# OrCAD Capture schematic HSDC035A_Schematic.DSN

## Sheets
1 PAGE3 - HARDWARE: title: TUSB1002AEVM  / HARDWARE; rev: A; note: HSDC035
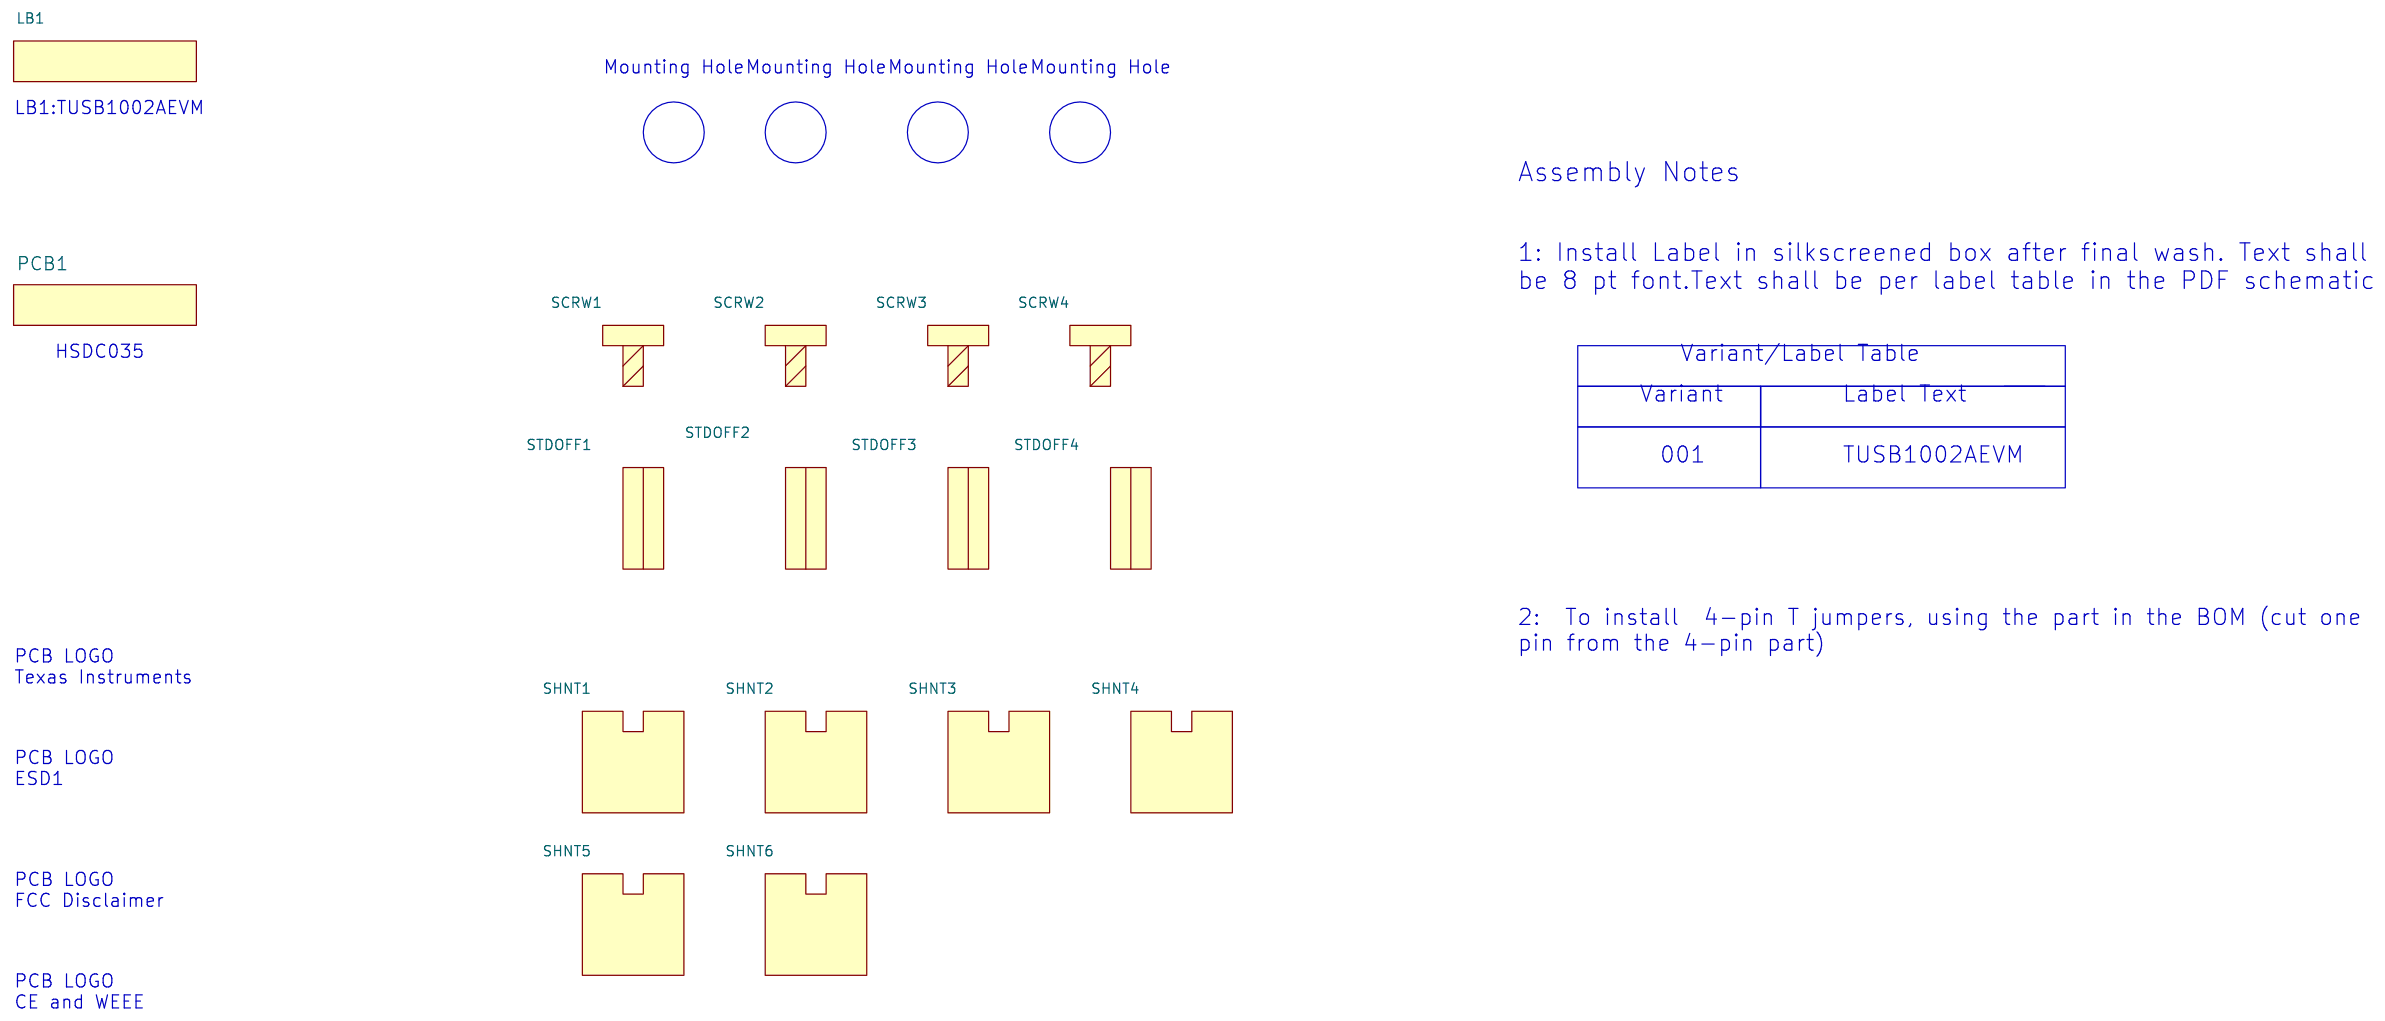
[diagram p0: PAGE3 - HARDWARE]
2 PAGE2 - CONFIG: size B; title: TUSB1002AEVM  / CONFIG; note: 6590969
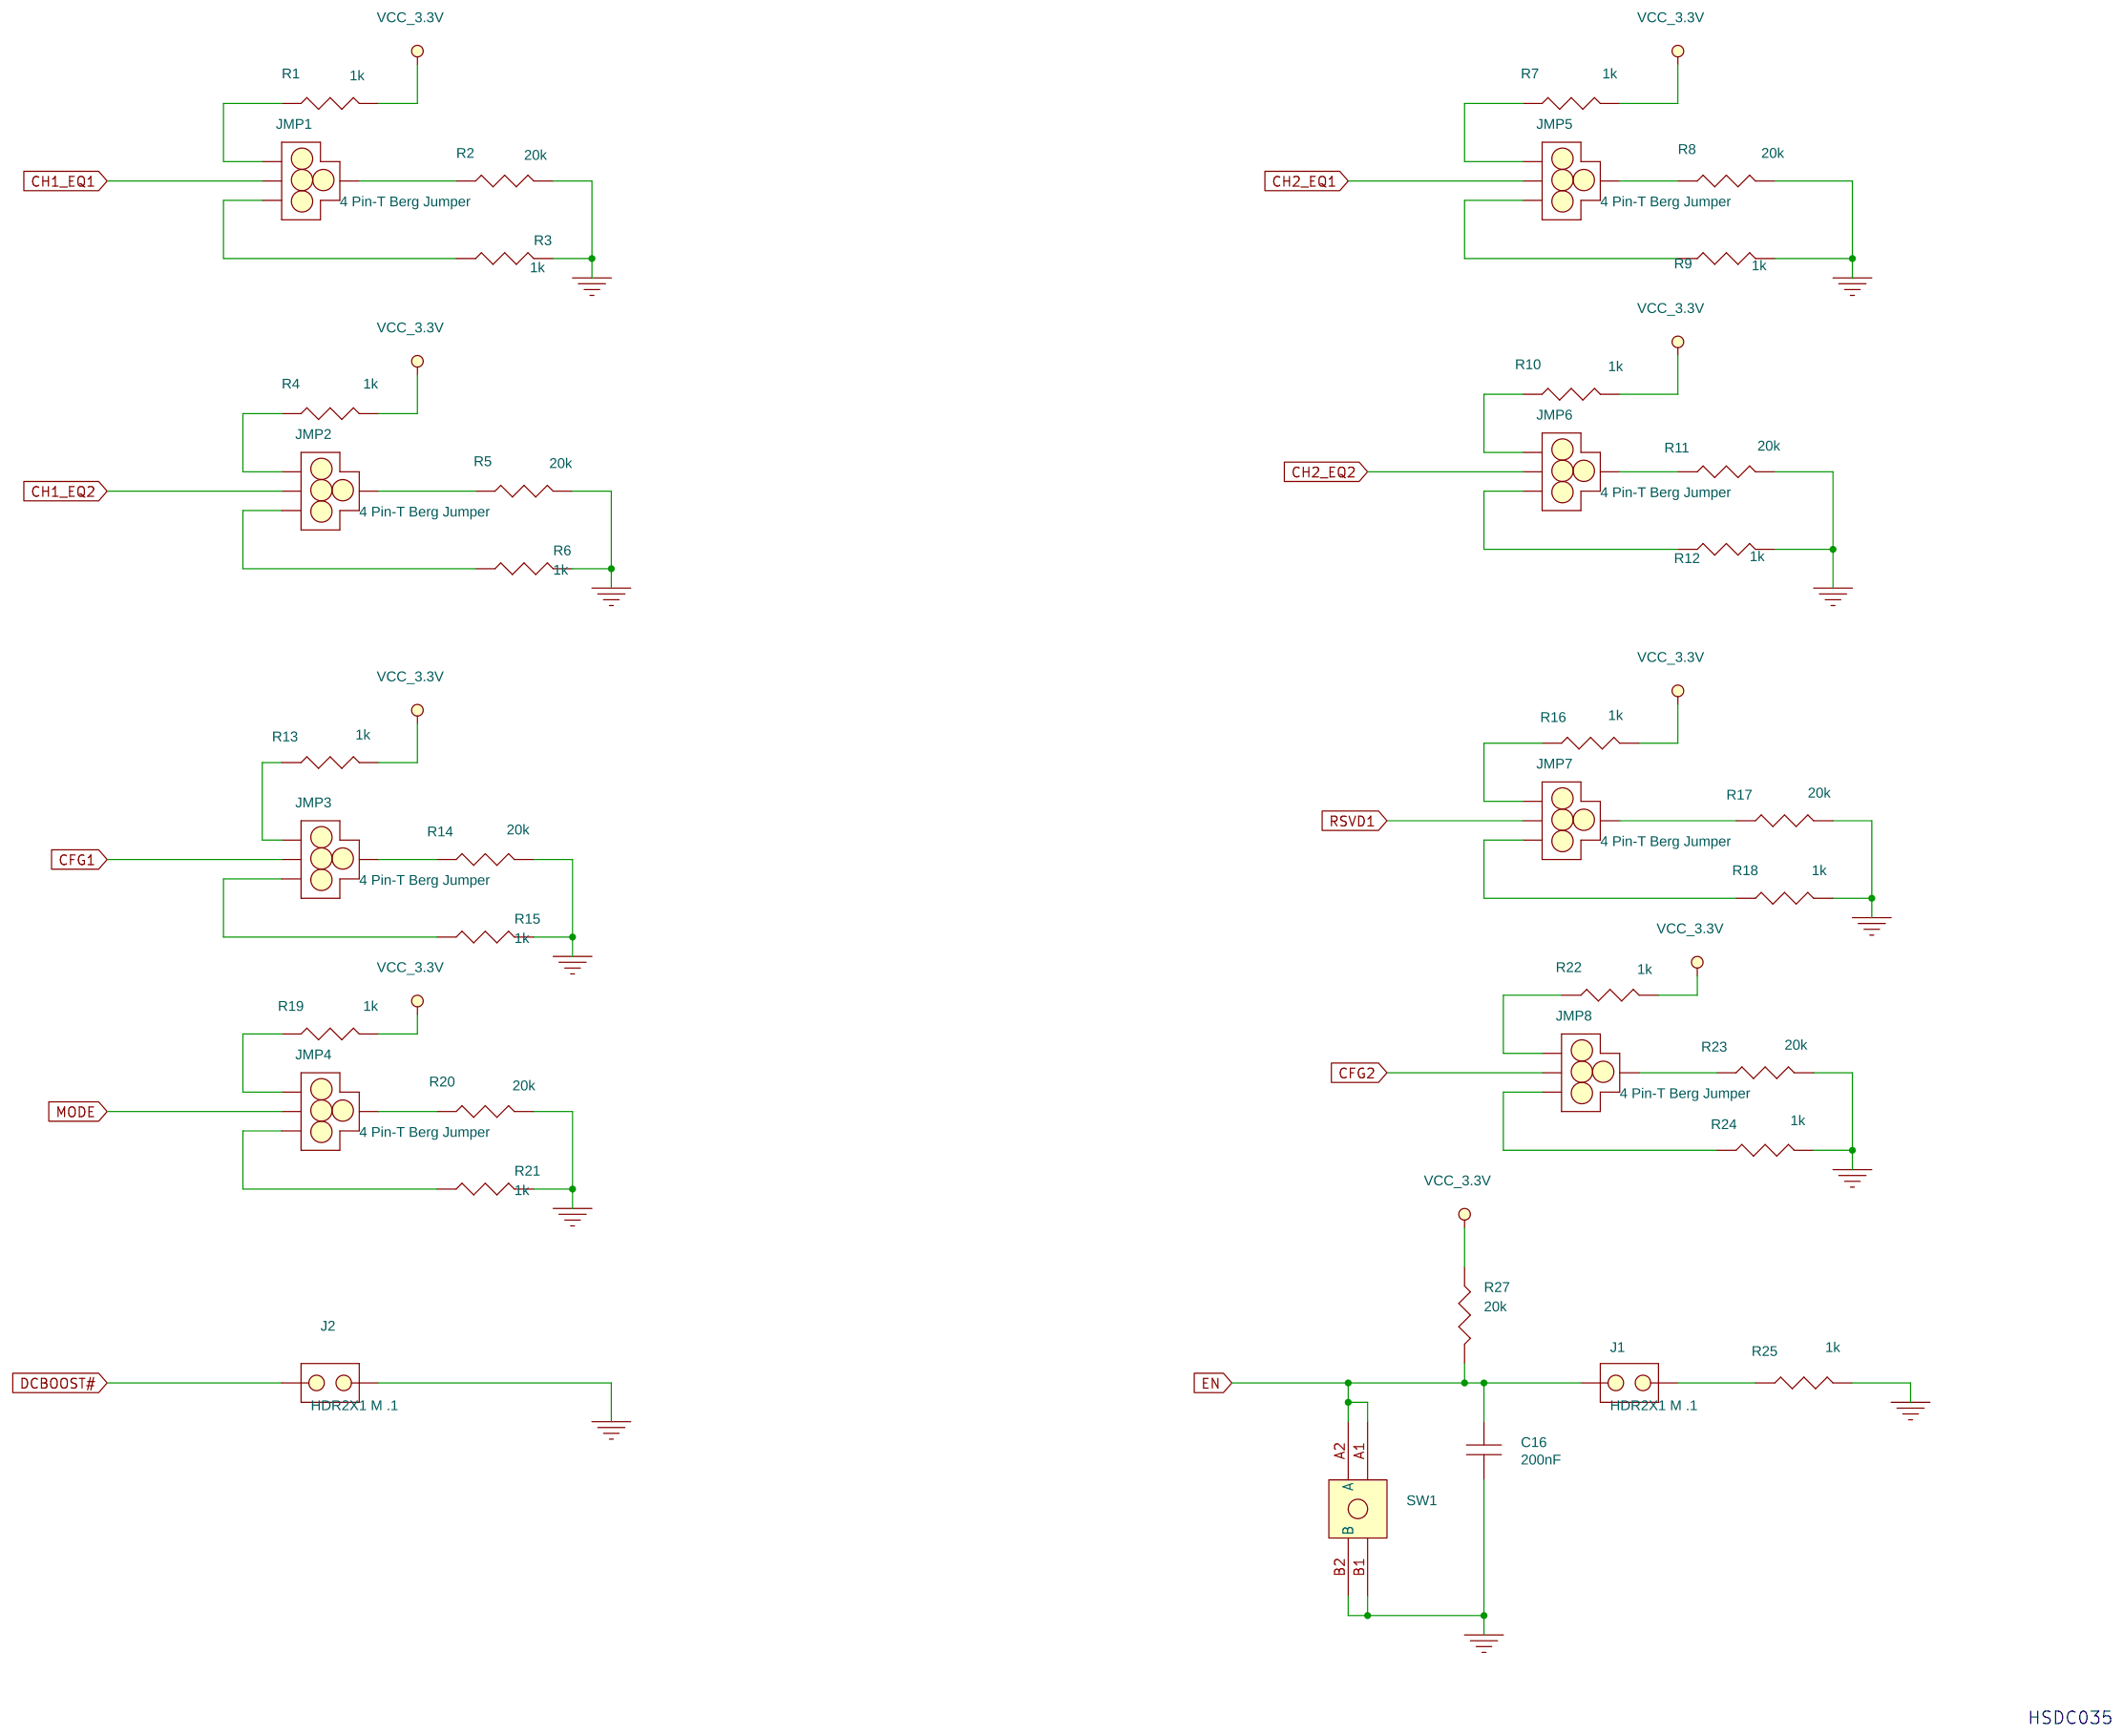
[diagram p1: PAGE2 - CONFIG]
3 PAGE1 - HighSpeed/Power: size B; title: TUSB1002AEVM / High-Speed/Power; note: 6590969
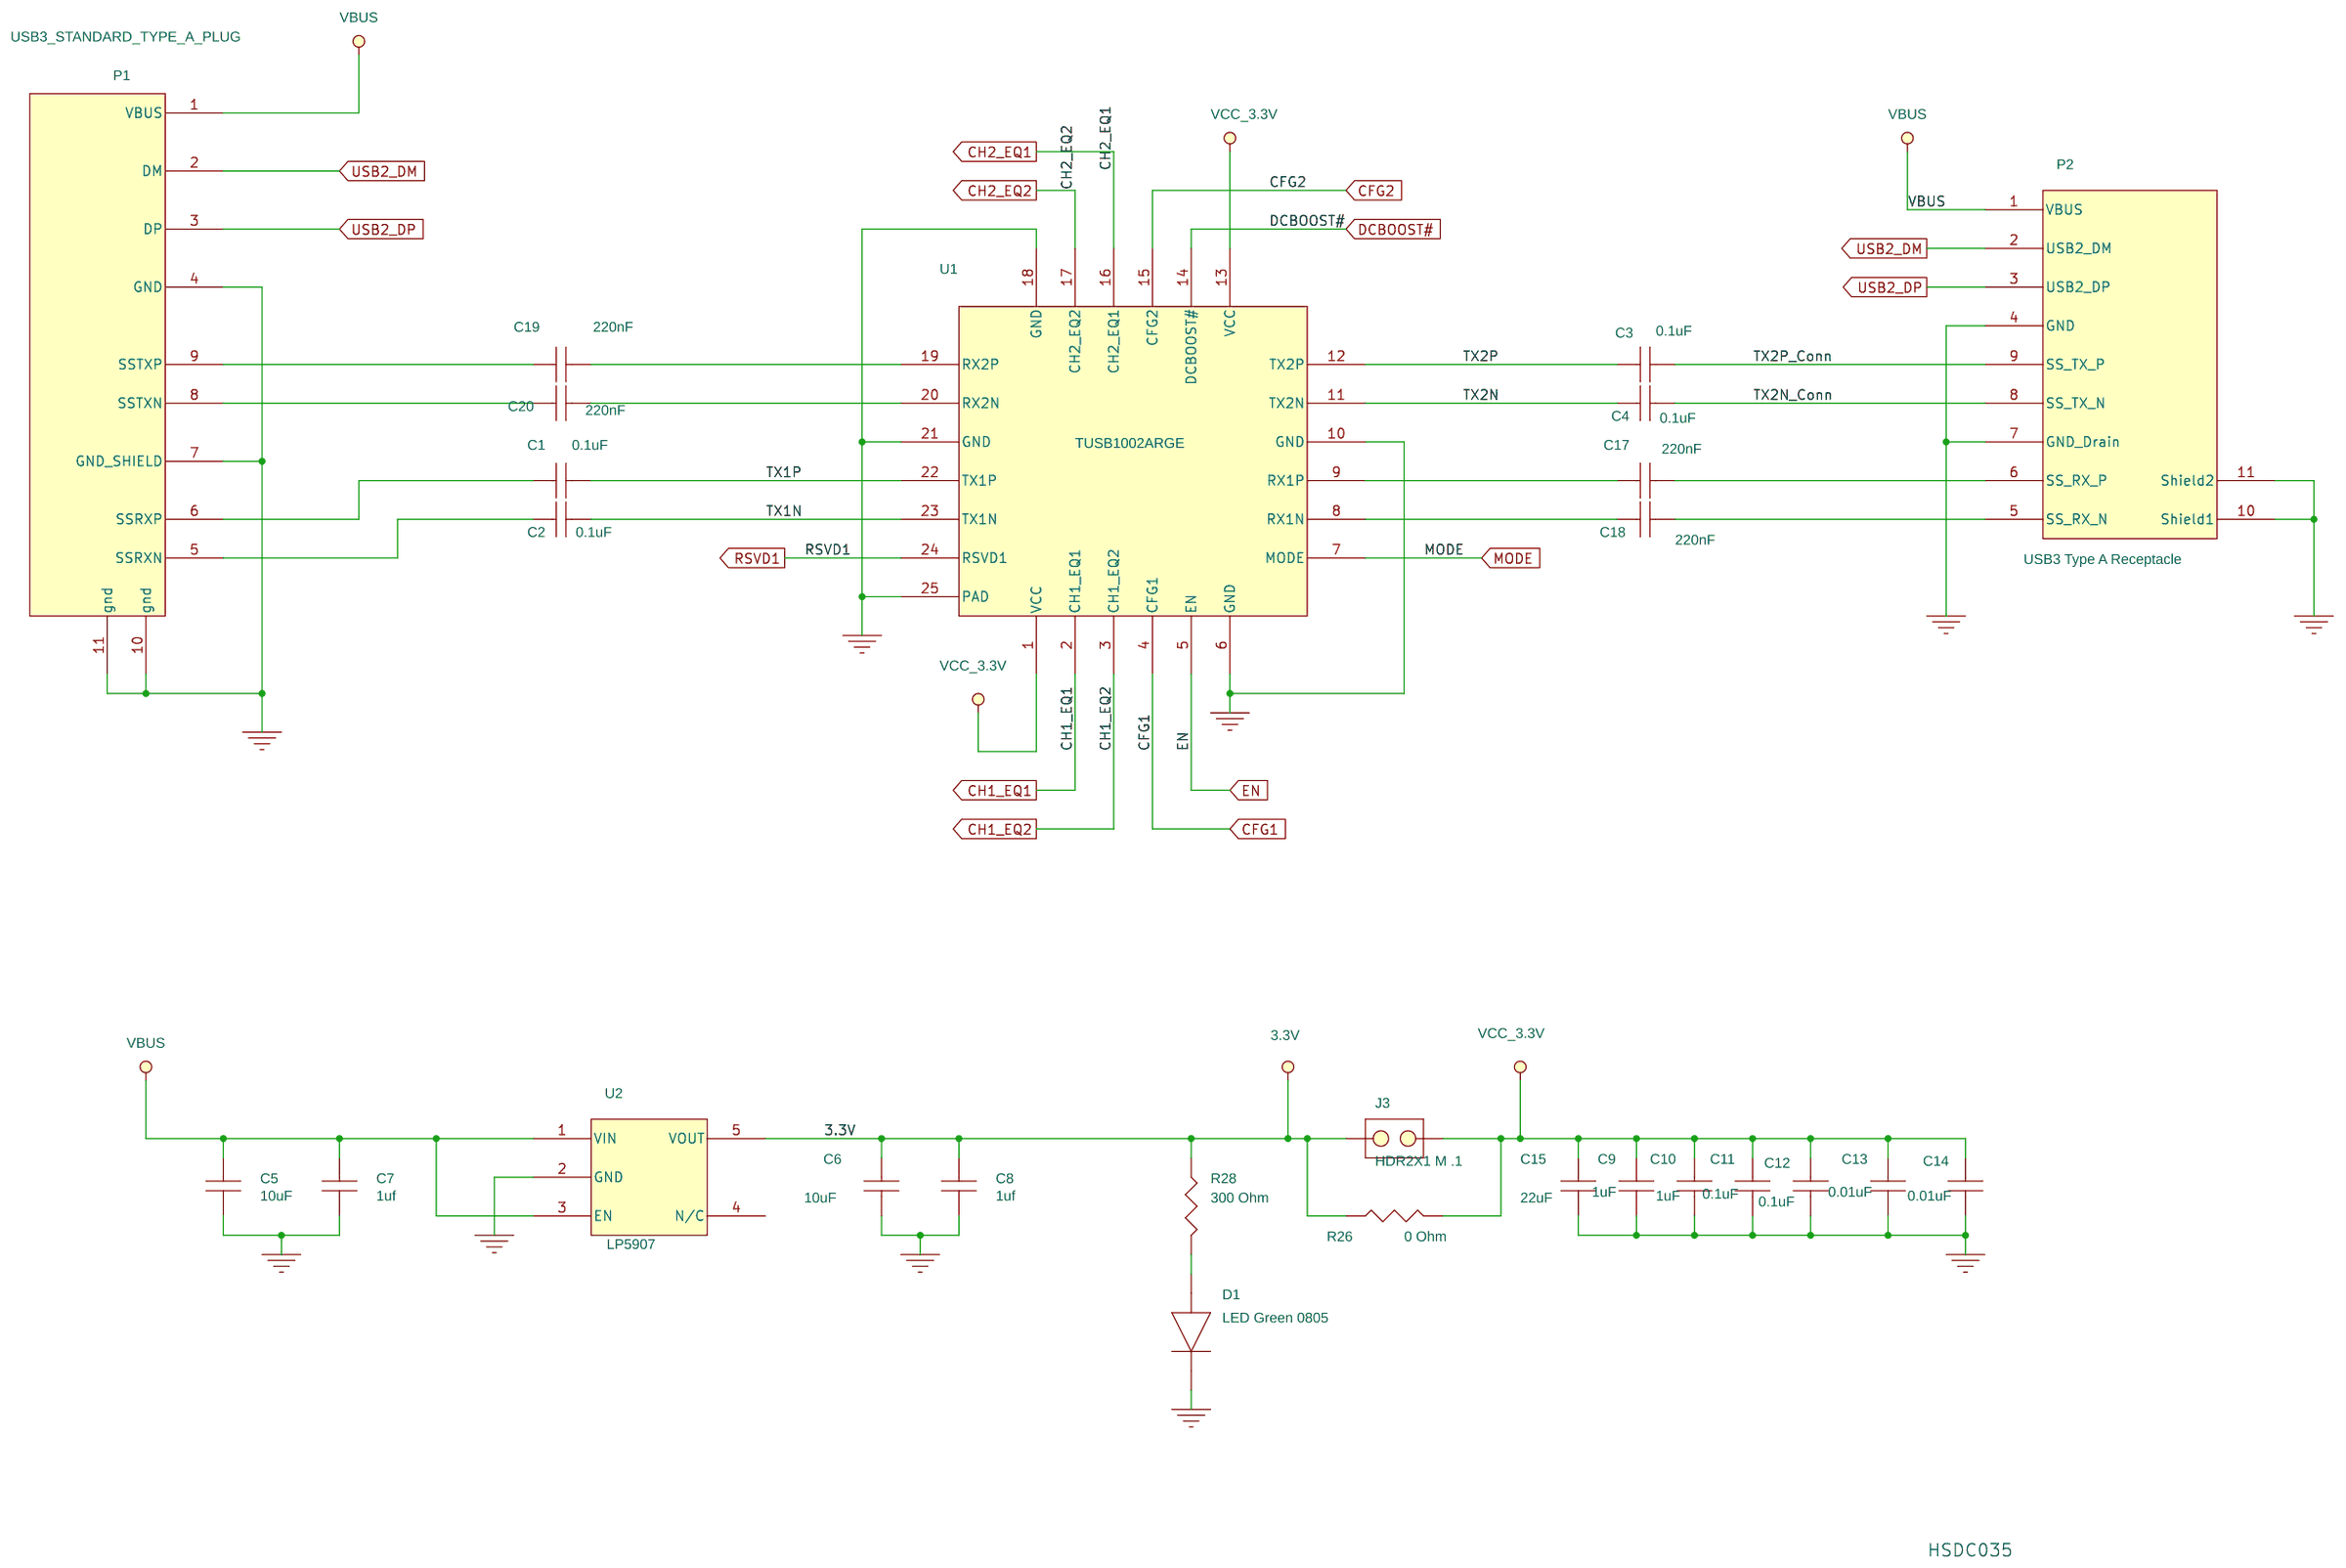
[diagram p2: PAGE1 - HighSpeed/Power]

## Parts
sheet PAGE1 - HighSpeed/Power
C1  0.1uF  [C0201]
C2  0.1uF  [C0201]
C3  0.1uF  [C0201]
C4  0.1uF  [C0201]
C5  10uF  [C0805]
C6  10uF  [C0805]
C7  1uf  [C0603]
C8  1uf  [C0603]
C9  1uF  [C0201]
C10  1uF  [C0201]
C11  0.1uF  [C0201]
C12  0.1uF  [C0201]
C13  0.01uF  [C0201]
C14  0.01uF  [C0201]
C15  22uF  [C0805]
C17  220nF  [C0201]
C18  220nF  [C0201]
C19  220nF  [C0201]
C20  220nF  [C0201]
D1  LED Green 0805  [led_0805]
J3  HDR2X1 M .1  [HDR_THVT_1x2_100]
P1  USB3_STANDARD_TYPE_A_PLUG  [CON_SMRT_USB3A_AMP]
P2  USB3 Type A Receptacle  [USB3_TYPEA]
R26  0 Ohm  [R0805]
R28  300 Ohm  [R0402]
U1  TUSB1002ARGE  [SKT_TUSB1002RGE]
U2  LP5907  [DBV_R-PDSO-G5]
sheet PAGE2 - CONFIG
C16  200nF  [C0402]
J1  HDR2X1 M .1  [HDR_THVT_1x2_100]
J2  HDR2X1 M .1  [HDR_THVT_1x2_100]
JMP1  4 Pin-T Berg Jumper  [berg2x3tee]
JMP2  4 Pin-T Berg Jumper  [berg2x3tee]
JMP3  4 Pin-T Berg Jumper  [berg2x3tee]
JMP4  4 Pin-T Berg Jumper  [berg2x3tee]
JMP5  4 Pin-T Berg Jumper  [berg2x3tee]
JMP6  4 Pin-T Berg Jumper  [berg2x3tee]
JMP7  4 Pin-T Berg Jumper  [berg2x3tee]
JMP8  4 Pin-T Berg Jumper  [berg2x3tee]
R1  1k  [R0402]
R2  20k  [R0402]
R3  1k  [R0402]
R4  1k  [R0402]
R5  20k  [R0402]
R6  1k  [R0402]
R7  1k  [R0402]
R8  20k  [R0402]
R9  1k  [R0402]
R10  1k  [R0402]
R11  20k  [R0402]
R12  1k  [R0402]
R13  1k  [R0402]
R14  20k  [R0402]
R15  1k  [R0402]
R16  1k  [R0402]
R17  20k  [R0402]
R18  1k  [R0402]
R19  1k  [R0402]
R20  20k  [R0402]
R21  1k  [R0402]
R22  1k  [R0402]
R23  20k  [R0402]
R24  1k  [R0402]
R25  1k  [R0402]
R27  20k  [R0402]
SW1  Switch - Push Button  [SW_THVT_EVQPAX05]
sheet PAGE3 - HARDWARE
LB1  Label  [rectangle]
PCB1  Label  [rectangle]
SCRW1  NY PMS 440 005 PH  [screw]
SCRW2  NY PMS 440 005 PH  [screw]
SCRW3  NY PMS 440 005 PH  [screw]
SCRW4  NY PMS 440 005 PH  [screw]
SHNT1  QPC02SXGN-RC  [.1]
SHNT2  QPC02SXGN-RC  [.1]
SHNT3  QPC02SXGN-RC  [.1]
SHNT4  QPC02SXGN-RC  [.1]
SHNT5  QPC02SXGN-RC  [.1]
SHNT6  QPC02SXGN-RC  [.1]
STDOFF1  1902E  [Standoff]
STDOFF2  1902E  [Standoff]
STDOFF3  1902E  [Standoff]
STDOFF4  1902E  [Standoff]

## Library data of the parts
C1-C4 C9-C14 C17-C20 = cc0201
C5 C6 C15 = cc0805
C7 C8 = cc0603_1.0uf_25V
D1 = LED_Green_0805_0
J1-J3 = HDR2X1_M_.1
P1 = USB3_STANDARD_TYPE_A_PLUG_0
P2 = USB_3.0_Type_A_Receptacle
R26 = r0805
R1-R25 R27 R28 = r0402
U1 = TUSB1002RGE_0
U2 = LP5907
C16 = cc0402
JMP1-JMP8 = 4_Pin-T_Berg_Jumper_0
SW1 = Switch_-_Push_Button_0
LB1 PCB1 = Label
SCRW1-SCRW4 = Screw_40x.5_Nylon
SHNT1-SHNT6 = Shunt
STDOFF1-STDOFF4 = Standoff

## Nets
3.3V: C6.1 C8.1 J3.1 R26.1 R28.1 U2.5(VOUT)
GND: C5.2 C6.2 C7.2 C8.2 C9.2 C10.2 C11.2 C12.2 C13.2 C14.2 C15.2 C16.2 D1.1(CATHODE) J2.2 P1.4(GND) P1.7(GND_SHIELD) P1.10(gnd) P1.11(gnd) P2.4(GND) P2.7(GND_Drain) P2.10(Shield1) P2.11(Shield2) R2.2 R3.2 R5.2 R6.2 R8.2 R9.2 R11.2 R12.2 R14.2 R15.2 R17.2 R18.2 R20.2 R21.2 R23.2 R24.2 R25.2 SW1.B1 SW1.B2(B) U1.6(GND) U1.10(GND) U1.18(GND) U1.21(GND) U1.25(PAD) U2.2(GND)
VBUS: C5.1 C7.1 P1.1(VBUS) P2.1(VBUS) U2.1(VIN) U2.3(EN)
VCC_3.3V: C9.1 C10.1 C11.1 C12.1 C13.1 C14.1 C15.1 J3.2 R1.2 R4.2 R7.2 R10.2 R13.2 R16.2 R19.2 R22.2 R26.2 R27.1 U1.1(VCC) U1.13(VCC)
CFG1: JMP3.2 U1.4(CFG1)
CFG2: JMP8.2 U1.15(CFG2)
CH1_EQ1: JMP1.2 U1.2(CH1_EQ1)
CH1_EQ2: JMP2.2 U1.3(CH1_EQ2)
CH2_EQ1: JMP5.2 U1.16(CH2_EQ1)
CH2_EQ2: JMP6.2 U1.17(CH2_EQ2)
DCBOOST#: J2.1 U1.14(DCBOOST#)
EN: C16.1 J1.1 R27.2 SW1.A1 SW1.A2(A) U1.5(EN)
MODE: JMP4.2 U1.7(MODE)
RSVD1: JMP7.2 U1.24(RSVD1)
TX1N: C2.2 U1.23(TX1N)
TX1P: C1.2 U1.22(TX1P)
TX2N: C4.1 U1.11(TX2N)
TX2N_Conn: C4.2 P2.8(SS_TX_N)
TX2P: C3.1 U1.12(TX2P)
TX2P_Conn: C3.2 P2.9(SS_TX_P)
USB2_DM: P1.2(DM) P2.2(USB2_DM)
USB2_DP: P1.3(DP) P2.3(USB2_DP)
N04063: JMP1.1 R1.1
N04069: JMP1.4 R2.1
N04079: JMP1.3 R3.1
N04162: JMP2.1 R4.1
N04168: JMP2.4 R5.1
N04172: JMP2.3 R6.1
N04828: JMP3.4 R14.1
N05600: JMP7.4 R17.1
N05896: J1.2 R25.1
N16532433: D1.2(ANNODE) R28.2
N16632710: C2.1 P1.5(SSRXN)
N16632722: C1.1 P1.6(SSRXP)
N16635768: JMP3.3 R15.1
N16635786: JMP3.1 R13.1
N16636225: JMP4.4 R20.1
N16636229: JMP4.1 R19.1
N16636241: JMP4.3 R21.1
N16636785: JMP5.4 R8.1
N16636789: JMP5.3 R9.1
N16636801: JMP5.1 R7.1
N16637091: JMP6.1 R10.1
N16637103: JMP6.3 R12.1
N16637121: JMP6.4 R11.1
N16637440: JMP7.1 R16.1
N16637452: JMP7.3 R18.1
N16637756: JMP8.1 R22.1
N16637768: JMP8.3 R24.1
N16637780: JMP8.4 R23.1
N16640066: C19.2 U1.19(RX2P)
N16640070: C19.1 P1.9(SSTXP)
N16640074: C20.1 P1.8(SSTXN)
N16640078: C20.2 U1.20(RX2N)
N16640102: C17.2 P2.6(SS_RX_P)
N16640106: C18.2 P2.5(SS_RX_N)
N16640110: C18.1 U1.8(RX1N)
N16640114: C17.1 U1.9(RX1P)

Not connected (* = marked no-connect by the designer): U2 4(N/C)

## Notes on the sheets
sheet 1
- Mounting Hole
- Mounting Hole
- Mounting Hole
- Mounting Hole
- LB1:TUSB1002AEVM
- Assembly Notes
- 1: Install Label in silkscreened box after final wash. Text shall
  be 8 pt font.Text shall be per label table in the PDF schematic
- HSDC035
- Variant/Label Table
- Variant
- Label Text
- 001
- TUSB1002AEVM
- 2:  To install  4-pin T jumpers, using the part in the BOM (cut one
  pin from the 4-pin part)
- PCB LOGO
  Texas Instruments
- PCB LOGO
  ESD1
- PCB LOGO
  FCC Disclaimer
- PCB LOGO
  CE and WEEE
sheet 2
- HSDC035
sheet 3
- HSDC035
